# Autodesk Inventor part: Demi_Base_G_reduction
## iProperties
Shininess: 64.0
Length Units: 11269
Angle Units: 11279
Time Units: 11290
Mass Units: 11283
Length Display Precision: 3
Angle Display Precision: 2
Compacted: True
Part Number: Demi_Base_G_reduction
Document SubType Name: Modeling
Created: 2008-02
Material: Acier doux
Designer: Pascal
Density: 7.86 g/cm^3
Density: 0.0
Volumn: 0.0
Area: 0.0
PropertySet Name: Model Information
Control State: 0
Master: False
Checked Out: False
MATIERE_PIECE: X2CrNi 18-11
OBSERVATIONS: Tôle ep. 15/10
DESIGNATION: Demi-réduction gauche
Author: Pascal
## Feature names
1. Lissage1
2. Coque1
3. Extrusion1
